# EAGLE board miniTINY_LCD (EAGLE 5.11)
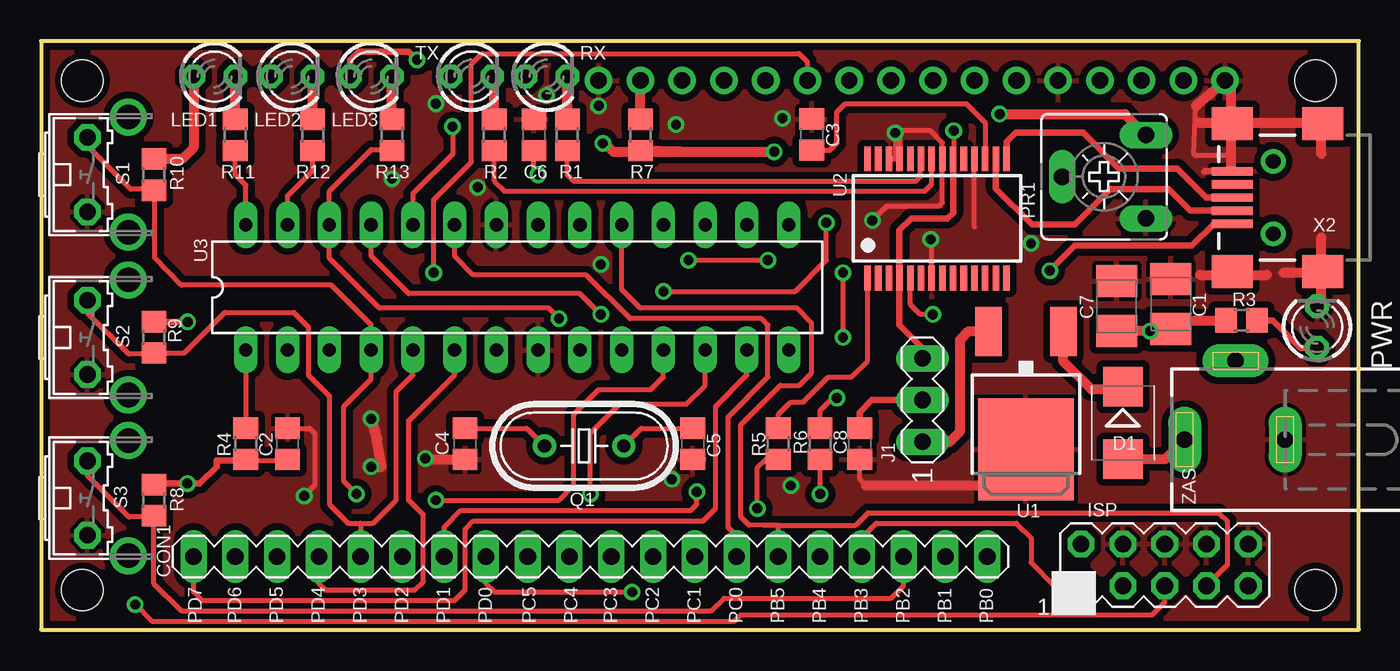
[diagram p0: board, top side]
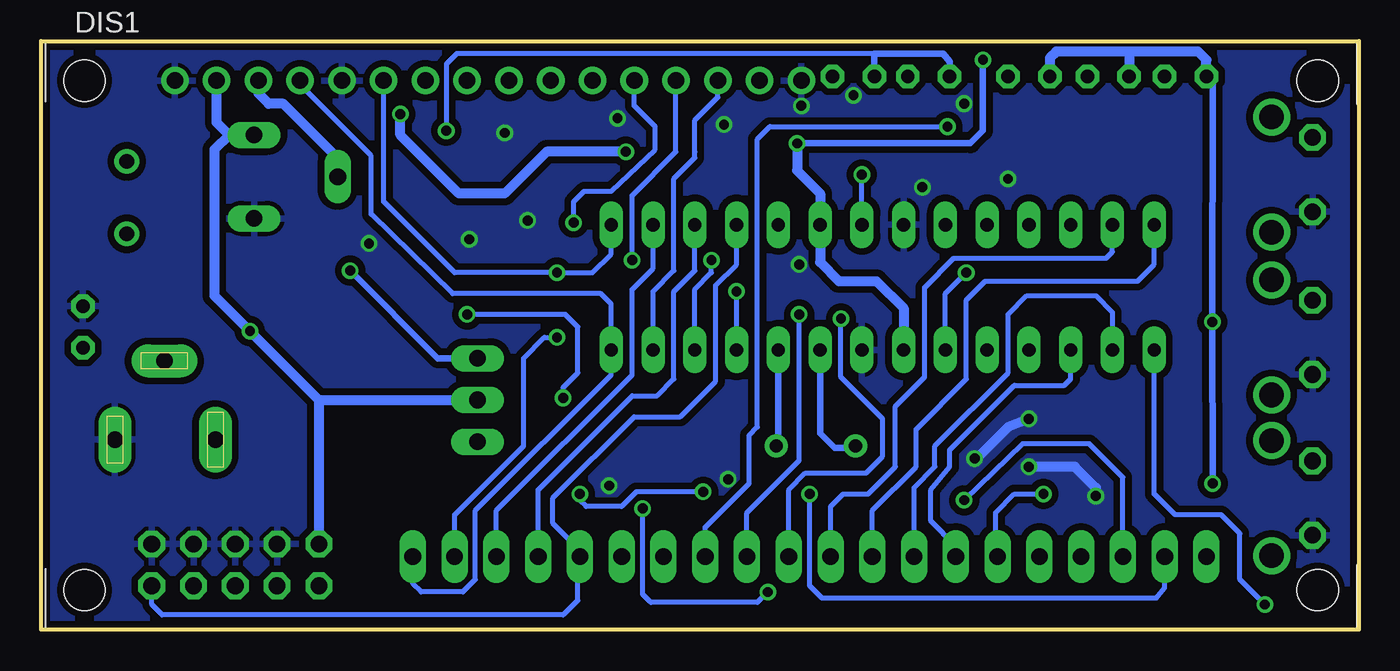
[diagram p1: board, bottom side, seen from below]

Size 80.14 x 35.81 mm. Coordinates in mm from the lower left corner, seen from the top.
Outline: 80.14,0 80.14,35.81 0,35.81 0,0 80.14,0
Copper layers (1*16): Top 0.035mm / dielectric 1.5mm / Bottom 0.035mm
Design rules "default *": minimum track width 8mil, minimum drill 16mil, track to track 8mil, track to pad 8mil, pad to pad 8mil, via to via 8mil, smd to smd 8mil, copper to edge 8mil, drill to drill 8mil, minimum pad ring 12mil, minimum via ring 8mil, stop-mask expansion 4mil, vias tented up to drill 18mil, thermal gap 10mil

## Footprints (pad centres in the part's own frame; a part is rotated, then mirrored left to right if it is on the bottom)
B/3528-21R = smd 1.95 x 2.5: + 1.525,0; - -1.525,0
C0805 = smd 1.3 x 1.5: 1 -0.95,0; 2 0.95,0
MA20-1 = drill 1.016 pad 1.473 long: 1 -24.13,0; 2 -21.59,0; 3 -19.05,0; 4 -16.51,0; 5 -13.97,0; 6 -11.43,0; 7 -8.89,0; 8 -6.35,0; 9 -3.81,0; 10 -1.27,0; 11 1.27,0; 12 3.81,0; 13 6.35,0; 14 8.89,0; 15 11.43,0; 16 13.97,0; 17 16.51,0; 18 19.05,0; 19 21.59,0; 20 24.13,0
SMB = smd 2.4 x 2.4: A 2.2,0; C -2.2,0
TUXGR_16X2_R2 = drill 1 pad 1.676 round: 1 -32,15.5; 2 -29.46,15.5; 3 -26.92,15.5; 4 -24.38,15.5; 5 -21.84,15.5; 6 -19.3,15.5; 7 -16.76,15.5; 8 -14.22,15.5; 9 -11.68,15.5; 10 -9.14,15.5; 11 -6.6,15.5; 12 -4.06,15.5; 13 -1.52,15.5; 14 1.02,15.5; 15 3.56,15.5; 16 6.1,15.5 | hole 2.5: -37.5,-15.5; 37.5,-15.5; -37.5,15.5; 37.5,15.5
MA05-2 = drill 1.016 octagon: 1 -5.08,-1.27; 2 -5.08,1.27; 3 -2.54,-1.27; 4 -2.54,1.27; 5 0,-1.27; 6 0,1.27; 7 2.54,-1.27; 8 2.54,1.27; 9 5.08,-1.27; 10 5.08,1.27
MA03-1 = drill 1.016 long: 1 -2.54,0; 2 0,0; 3 2.54,0
LED3MM = drill 0.813 octagon: A -1.27,0; K 1.27,0
CA6V = drill 1.016 long: A -2.54,-2.54; E 2.54,-2.54; S 0,2.54
HC49U70 = drill 0.813 round: 1 -2.413,0; 2 2.413,0
R0805 = smd 1.3 x 1.5: 1 -0.95,0; 2 0.95,0
B3F-31XX = drill 1.016 octagon: 1 -2.261,-1.245; 2 2.261,-1.245 | drill 1.499 pad 2.159 round: 3 -3.505,1.245; 4 3.505,1.245
DPACK = smd 1.6 x 3: 1 -2.28,-4.8; 3 2.28,-4.8 | smd 5.8 x 6.2: 4 0,2.38
SSOP28 = smd 0.4 x 1.5: 1 -4.225,-3.625; 2 -3.575,-3.625; 3 -2.925,-3.625; 4 -2.275,-3.625; 5 -1.625,-3.625; 6 -0.975,-3.625; 7 -0.325,-3.625; 8 0.325,-3.625; 9 0.975,-3.625; 10 1.625,-3.625; 11 2.275,-3.625; 12 2.925,-3.625; 13 3.575,-3.625; 14 4.225,-3.625; 15 4.225,3.625; 16 3.575,3.625; 17 2.925,3.625; 18 2.275,3.625; 19 1.625,3.625; 20 0.975,3.625; 21 0.325,3.625; 22 -0.325,3.625; 23 -0.975,3.625; 24 -1.625,3.625; 25 -2.275,3.625; 26 -2.925,3.625; 27 -3.575,3.625; 28 -4.225,3.625
DIL28-3 = drill 0.813 long: 1 -16.51,-3.81; 2 -13.97,-3.81; 3 -11.43,-3.81; 4 -8.89,-3.81; 5 -6.35,-3.81; 6 -3.81,-3.81; 7 -1.27,-3.81; 8 1.27,-3.81; 9 3.81,-3.81; 10 6.35,-3.81; 11 8.89,-3.81; 12 11.43,-3.81; 13 13.97,-3.81; 14 16.51,-3.81; 15 16.51,3.81; 16 13.97,3.81; 17 11.43,3.81; 18 8.89,3.81; 19 6.35,3.81; 20 3.81,3.81; 21 1.27,3.81; 22 -1.27,3.81; 23 -3.81,3.81; 24 -6.35,3.81; 25 -8.89,3.81; 26 -11.43,3.81; 27 -13.97,3.81; 28 -16.51,3.81
USB-MINIB-NOSTOP = smd 2.5 x 0.5: D+ 2.5,0; D- 2.5,0.8; GND 2.5,-1.6; ID 2.5,-0.8; VBUS 2.5,1.6 | smd 2.5 x 2: G1 -3,-4.5; G2 -3,4.5; G3 2.5,4.5; G4 2.5,-4.5 | drill 0.9 pad 0.8 round: H1 0,2.2 | drill 0.9 pad 0.787 round: H2 0,-2.2
DCJ0202 = drill 1 pad 2 long: 1 0,3.1; 2 4.8,0; 3 0,-3

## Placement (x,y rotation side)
C1  10uF  [B/3528-21R]  68.71,19.81 270 top
C2  100nF  [C0805]  14.99,11.3 90 top
C3  100nF  [C0805]  46.86,30.12 90 top
C4  22pF  [C0805]  25.78,11.3 270 top
C5  22pF  [C0805]  39.62,11.3 270 top
C6  100nF  [C0805]  29.97,30.1 90 top
C7  10uF  [B/3528-21R]  65.41,19.68 270 top
C8  100nF  [C0805]  49.78,11.3 270 top
CON1  [MA20-1]  33.4,4.45 0 top
D1  [SMB]  65.79,12.57 270 top
DIS1  [TUXGR_16X2_R2]  40.01,17.91 0 bottom
ISP  [MA05-2]  68.33,3.94 0 top
J1  [MA03-1]  53.59,13.97 90 top
LED1  [LED3MM]  10.54,33.66 0 top
LED2  [LED3MM]  15.24,33.66 0 top
LED3  [LED3MM]  20.07,33.66 0 top
PR1  10k  [CA6V]  64.64,27.56 90 top
PWR  [LED3MM]  77.6,18.41 90 top
Q1  [HC49U70]  33.02,11.18 0 top
R1  1k  [R0805]  32,30.1 270 top
R2  1k  [R0805]  27.56,30.1 270 top
R3  1k  [R0805]  73,18.82 180 top
R4  10k  [R0805]  12.45,11.3 90 top
R5  1k  [R0805]  44.83,11.3 90 top
R6  1k  [R0805]  47.37,11.3 90 top
R7  68  [R0805]  36.45,30.1 270 top
R8  10k  [R0805]  6.86,7.87 270 top
R9  10k  [R0805]  6.86,17.78 270 top
R10  10k  [R0805]  6.86,27.69 270 top
R11  1k  [R0805]  11.81,30.1 270 top
R12  1k  [R0805]  16.51,30.1 270 top
R13  1k  [R0805]  21.34,30.1 270 top
RX  [LED3MM]  30.73,33.66 0 top
S1  [B3F-31XX]  4.06,27.69 270 top
S2  [B3F-31XX]  4.06,17.78 270 top
S3  [B3F-31XX]  4.06,8 270 top
TX  [LED3MM]  26.16,33.66 0 top
U1  78M05  [DPACK]  59.89,13.34 180 top
U2  FT232RL  [SSOP28]  54.48,25.02 0 top
U3  MEGA8-P  [DIL28-3]  28.96,20.83 0 top
X2  USB-SMD-NS  [USB-MINIB-NOSTOP]  74.93,26.29 180 top
ZAS  [DCJ0202]  72.64,11.56 90 top

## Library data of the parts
C1-C8 R1-R13 = rcl
CON1 = con-lstb; OC_FARNELL: unknown; OC_NEWARK: unknown
D1 = diode
DIS1 = display-lcd; OC_FARNELL: unknown; OC_NEWARK: unknown
ISP = con-lstb
J1 = con-lstb_v2a; OC_FARNELL: unknown; OC_NEWARK: unknown
LED1-LED3 PWR RX TX = led
PR1 = pot
Q1 = crystal; OC_FARNELL: unknown; OC_NEWARK: unknown
S1-S3 = switch-omron; MPN: B3F-3100; OC_FARNELL: 959704; OC_NEWARK: 36M3582
U1 = v-reg
U2 = ftdichip; MPN: FT232RL; OC_FARNELL: 1146032; OC_NEWARK: 91K9918
U3 = atmel; OC_FARNELL: unknown; OC_NEWARK: unknown
X2 = SparkFun
ZAS = con-jack; OC_FARNELL: unknown; OC_NEWARK: unknown

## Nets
+5V: C1.+ C2.1 C7.+ C8.1 DIS1.2 ISP.2 J1.2 LED1.A LED2.A LED3.A PR1.E R3.2 R4.1 R7.2 R8.1 R9.1 R10.1 U3.7 U3.20
AREF: C6.1 U3.21
GND: C1.- C2.2 C3.2 C4.2 C5.2 C6.2 C7.- C8.2 DIS1.1 DIS1.5 DIS1.16 ISP.4 ISP.6 ISP.8 ISP.10 PR1.A PWR.K S1.2 S2.2 S3.2 U1.4 U2.7 U2.18 U2.21 U2.25 U2.26 U3.8 U3.22 X2.GND ZAS.3
N$1: C3.1 U2.17
N$2: D1.A ZAS.1
N$3: D1.C U1.1
N$4: R1.2 U2.23
N$5: PWR.A R3.1
N$6: R2.2 U2.22
N$7: J1.1 U1.3
N$8: R1.1 RX.K
N$9: R2.1 TX.K
N$10: LED1.K R11.1
N$11: LED2.K R12.1
N$12: DIS1.15 R7.1
N$13: LED3.K R13.1
N$14: DIS1.3 PR1.S
N$31: U2.15 X2.D+
N$32: U2.16 X2.D-
N$40: C5.1 Q1.2 U3.10
N$41: C4.1 Q1.1 U3.9
PB0: CON1.20 DIS1.4 U3.14
PB1: CON1.19 DIS1.6 U3.15
PB2: CON1.18 R8.2 S3.1 U3.16
PB3/MOSI: CON1.17 ISP.1 U3.17
PB4/MISO: CON1.16 ISP.9 U3.18
PB5/SCK: CON1.15 ISP.7 U3.19
PC0/A0: CON1.14 U3.23
PC1/A1: CON1.13 U3.24
PC2/A2: CON1.12 U3.25
PC3/A3: CON1.11 R13.2 U3.26
PC4/A4: CON1.10 R12.2 U3.27
PC5/A5: CON1.9 R11.2 U3.28
PD0/RX: CON1.8 R5.1 U3.2
PD1/TX: CON1.7 R6.1 U3.3
PD2: CON1.6 R10.2 S1.1 U3.4
PD3: CON1.5 R9.2 S2.1 U3.5
PD4: CON1.4 DIS1.11 U3.6
PD5: CON1.3 DIS1.12 U3.11
PD6: CON1.2 DIS1.13 U3.12
PD7: CON1.1 DIS1.14 U3.13
RESET: ISP.5 R4.2 U3.1
RX: R5.2 U2.1
TX: R6.2 U2.5
VUSB: J1.3 RX.A TX.A U2.4 U2.20 X2.VBUS

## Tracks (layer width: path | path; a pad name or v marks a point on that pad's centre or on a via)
+5V  (via drill 0.6)
  Top 0.305: 12.45,10.29 14.92,10.29 C2.1
  Top 0.406: C8.1 49.77,13.22 50.52,13.97 J1.2 | v22.86,34.67 22.35,35.18 19.3,35.18 18.8,34.67 LED3.A | R9.1 7.93,18.73 v8.91,18.72 | R4.1 12.45,10.29 10.67,10.29 10.67,9.91 9.65,8.89 v8.89,8.89 6.92,8.89 R8.1
  Top 0.61: C7.+ 68.58,18.16 C1.+ 69.24,18.82 | 69.24,18.82 R3.2 | 69.24,18.82 68.1,18.82 v67.44,18.16 | R10.1 8.57,28.64 9.27,29.34 LED1.A | v34.16,29.59 34.29,29.59 34.8,29.08 38.93,29.08 | 38.93,29.08 R7.2 | 38.93,29.08 v44.58,29.08 | v58.29,31.37 65.91,31.37 PR1.E
  Bottom 0.406: v22.86,34.67 22.86,30.35 23.62,29.59 v34.16,29.59 | LED1.A 8.89,33.27 v8.91,18.72 v8.89,8.89
  Bottom 0.61: LED1.A 9.27,34.67 9.78,35.18 14.1,35.18 | U3.7 27.69,19.56 29.34,21.21 31.62,21.21 32.77,22.35 U3.20 32.77,26.54 34.16,27.94 v34.16,29.59 | 14.1,35.18 18.41,35.18 18.8,34.8 LED3.A | LED2.A 13.97,35.05 14.1,35.18 | DIS1.2 69.47,30.86 68.71,30.1 | PR1.E 68.71,30.1 | 63.25,13.97 J1.2 | 68.71,30.1 69.6,29.21 69.6,20.32 v67.44,18.16 63.25,13.97 | 63.25,13.97 ISP.2 | v44.58,29.08 49.4,29.08 51.94,26.54 54.74,26.54 58.29,30.1 v58.29,31.37
AREF  (via drill 0.6)
  Top 0.305: v30.23,27.69 30.23,27.81 29.97,28.07 C6.1
  Bottom 0.305: U3.21 v30.23,27.69
GND  (via drill 0.6)
  Top 0.305: v51.94,30.23 51.94,28.65 U2.26 | C8.2 49.78,9.14 50.16,8.76 | 57.7,8.76 U1.4 | C2.2 16.32,12.25 16.64,11.94 16.64,8.76 v16,8.13 | U2.7 54.16,23.31 53.98,23.5 | v50.55,24.89 51.44,25.78 54.61,25.78 54.81,25.98 U2.21 54.81,29.65 54.1,30.35 52.07,30.35 v51.94,30.23 | 56.76,24.52 U2.18 | 72.02,33.41 DIS1.1 | 70.23,31.88 70.1,28.96 70.23,28.83 72.26,28.83 72.39,28.7 72.39,28.07 72.39,27.93 X2.GND | U2.25 52.21,29.96 v51.94,30.23
  Top 0.406: 71.35,27.89 70.76,27.89 70.74,27.86
  Top 0.61: 50.16,8.76 57.7,8.76 | v20.07,9.91 20.7,9.91 20.4,11.59 | 20.4,11.59 20.32,12.06 v20.07,12.83 20.45,11.63 20.4,11.59 | C4.2 23.43,10.35 v23.37,10.41 | 70.23,31.88 72.02,33.41 | 72.39,28.07 72.39,33.53 | 77.85,28.96 77.85,30.61 | 70.36,30.86 77.98,30.86 | 70.48,21.59 74.55,21.59 | 75.56,21.72 77.98,21.72 | 77.85,19.94 77.85,23.88
  Bottom 0.61: v16,8.13 16,8.64 17.27,9.91 v20.07,9.91 | v23.37,10.41 23.24,10.41 21.34,12.32 v20.07,12.83
  other vias: 26.54,26.92 38.35,9.14 33.91,31.88 34.04,22.23 21.34,27.43 24,32 38.61,30.73 30.73,32.51 45.09,31.11 60.2,23.5 54.1,23.75 45.59,8.76
  pour Bottom (isolate 0.406): -0.25,36.83 80.9,36.83 81.03,-0.51 -0.64,-0.51 -0.64,36.45
  pour Top (isolate 0.406): -1.02,36.58 80.9,36.2 81.28,-0.89 -0.76,-0.89
N$1
  Top 0.305: C3.1 47.97,29.17 48.39,29.59 48.39,31.5 48.9,32 56.26,32 57.4,30.86 U2.17
N$2
  Top 0.61: D1.A 68.36,10.37 ZAS.1
N$3
  Top 0.61: U1.1 62.17,16.31 63.88,14.61 65.62,14.61 D1.C
N$4
  Top 0.305: R1.2 32,27.69 32.38,27.3 53.21,27.3 53.47,27.56 53.47,28.6 U2.23 53.47,28.68
N$5
  Top 0.406: R3.1 74.91,18.82 76.58,17.14 PWR.A
N$6
  Top 0.305: U2.22 54.16,27.11 53.72,26.67 28.19,26.67 27.56,27.3 R2.2
N$7
  Top 0.61: J1.1 55.24,11.43 55.88,12.06 55.88,17.65 56.39,18.16 57.51,18.16 U1.3
N$8
  Top 0.61: R1.1 31.94,31.05 32,31.88 RX.K
N$9
  Top 0.61: TX.K 27.56,33.66 R2.1
N$10
  Top 0.61: R11.1 LED1.K
N$11
  Top 0.61: R12.1 LED2.K
N$12
  Top 0.61: DIS1.15 R7.1
N$13
  Top 0.61: R13.1 LED3.K
N$14
  Bottom 0.61: DIS1.3 66.92,32.63 66.29,32 65.41,32 62.1,28.7 PR1.S
N$31
  Top 0.406: X2.D+ 70.87,26.29 69.09,28.07 65.53,28.07 63.37,30.23 59.26,30.23 58.73,29.69 58.73,28.66 U2.15
N$32
  Top 0.406: X2.D- 69.89,25.49 68.58,26.8 65.02,26.8 62.87,24.64 60.27,24.64 58.06,26.85 U2.16
N$40
  Top 0.305: C5.1 36.51,12.25 Q1.2
  Bottom 0.406: U3.10 35.31,11.3 Q1.2
N$41
  Top 0.305: C4.1 29.53,12.25 Q1.1
  Bottom 0.406: U3.9 32.77,11.94 31.88,11.05 30.73,11.05 Q1.1
PB0
  Bottom 0.305: DIS1.4 64.39,33.27 64.39,33.15 60.07,28.83 60.07,25.27 55.12,20.45 46.1,20.45 45.47,19.81 U3.14 45.47,15.49 53.72,7.24 53.72,3.05 54.48,2.29 57.02,2.29 57.53,2.79 CON1.20
PB1  (via drill 0.6)
  Top 0.305: v48.77,17.78 v48.77,21.72
  Bottom 0.305: v48.77,17.78 49.53,17.78 50.8,16.51 50.8,11.18 54.99,6.99 CON1.19 | DIS1.6 59.31,26.04 54.99,21.72 v48.77,21.72 46.61,21.72 45.47,22.86 U3.15
PB2
  Top 0.305: S3.1 2.82,9.37 5.33,6.86 6.79,6.86 R8.2 6.86,2.79 8.51,1.14 40.77,1.14 41.53,1.91 51.69,1.91 52.45,2.67 CON1.18
  Bottom 0.305: U3.16 42.93,21.97 44.2,20.7 44.2,15.49 52.45,7.24 CON1.18
PB3/MOSI
  Top 0.305: ISP.1 61.59,2.67 60.2,4.06 60.2,5.59 59.31,6.48 50.8,6.48 49.91,5.59 CON1.17
  Bottom 0.305: U3.17 40.39,21.84 41.66,20.57 41.66,15.24 42.67,14.22 44.2,14.22 49.91,8.51 CON1.17
PB4/MISO
  Bottom 0.305: ISP.9 73.41,1.52 72.77,0.89 48.39,0.89 47.5,1.78 47.5,4.32 | CON1.16 47.37,4.83 49.02,6.48 49.02,8 44.07,12.95 41.27,12.95 39.12,15.11 39.12,20.95 37.85,22.23 U3.18
  Bottom 0.406: 47.5,4.32 CON1.16
PB5/SCK
  Top 0.305: U3.19 35.31,20.7 36.45,19.56 45.97,19.56 46.86,18.67 46.86,15.62 46.1,14.86 44.96,14.86 42.55,12.45 42.55,9.91 42.55,6.87 43.03,6.37 43.94,6.35 44.83,6.35 | ISP.7 72.14,3.94 72.14,6.6 71.63,7.11 50.29,7.11 49.53,6.35 44.83,6.35 | CON1.15 44.83,6.35
PC0/A0
  Top 0.305: CON1.14 42.29,5.71 41.78,6.22 41.78,12.95 44.2,15.37 44.2,18.54 43.81,18.92 35.81,18.92 33.15,21.59 26.29,21.59 25.15,22.73 U3.23
PC1/A1  (via drill 0.6)
  Top 0.305: v25.02,30.61 25.02,28.93 22.61,26.54 U3.24
  Bottom 0.305: CON1.13 39.75,6.22 37.08,8.89 37.08,11.81 36.58,12.32 36.58,29.84 35.81,30.61 v25.02,30.61
PC2/A2  (via drill 0.6)
  Top 0.305: v34.04,19.18 32.77,20.45 22.35,20.45 20.07,22.73 U3.25
  Bottom 0.305: CON1.12 37.21,7.11 34.04,10.29 v34.04,19.18
PC3/A3  (via drill 0.6)
  Top 0.305: v31.5,18.92 30.86,19.56 20.57,19.56 17.53,22.61 U3.26 17.53,26.67 20.07,29.21 21.27,29.21 R13.2
  Bottom 0.305: CON1.11 34.67,8.51 33.66,9.53 29.97,9.53 28.96,10.54 28.96,12.83 31.5,15.37 v31.5,18.92
PC4/A4
  Top 0.305: R12.2 16.51,27.94 14.99,26.42 U3.27
  Bottom 0.305: CON1.10 32.13,7.49 31.37,8.26 29.84,8.26 28.19,9.91 28.19,13.59 26.42,15.37 26.42,20.83 24.64,22.61 15.37,22.61 14.99,22.99 U3.27
PC5/A5
  Top 0.305: R11.2 11.81,27.69 12.45,27.05 U3.28
  Bottom 0.305: CON1.9 29.59,7.24 26.92,9.91 26.92,12.19 23.88,15.24 23.88,20.07 22.73,21.21 13.46,21.21 12.45,22.23 U3.28
PD0/RX  (via drill 0.6)
  Top 0.305: v43.56,7.37 43.56,9.86 44.07,10.36 R5.1 | v35.94,2.29 27.56,2.29 27.05,2.79 CON1.8
  Bottom 0.305: CON1.8 27.05,8.64 25.78,9.91 25.78,11.18 21.34,15.62 21.34,19.18 20.19,20.32 16,20.32 14.99,19.3 U3.2 | v43.56,7.37 43.56,2.16 43.05,1.65 36.58,1.65 v35.94,2.29
PD1/TX  (via drill 0.6)
  Top 0.305: CON1.7 24.51,6.22 25.53,7.24 39.5,7.24 39.88,7.62 v39.88,8.38 | v47.37,8.26 R6.1
  Bottom 0.305: CON1.7 24.51,5.08 26.04,6.6 26.04,8.51 24.89,9.91 24.89,10.92 20.95,14.86 17.91,14.86 17.53,15.24 U3.3 | v39.88,8.38 43.94,8.38 44.83,7.49 46.99,7.49 47.37,7.87 v47.37,8.26
PD2  (via drill 0.6)
  Top 0.305: v19.18,8.26 18.41,9.02 18.41,13.59 20.07,15.24 U3.4 20.07,18.54 17.65,20.95 8.53,20.95 6.91,22.63 6.92,26.8 R10.2 6.8,26.8 5.46,26.8 2.82,29.44 S1.1
  Bottom 0.305: v19.18,8.26 20.95,8.26 22.1,7.11 22.1,4.57 CON1.6
PD3
  Top 0.305: U3.5 22.61,15.49 21.59,14.48 21.59,7.87 20.19,6.48 19.43,6.48 | 19.43,6.48 CON1.5 | 19.43,6.48 18.67,6.48 17.53,7.62 17.53,14.22 16.26,15.49 16.26,18.41 15.37,19.3 11.18,19.3 8.7,16.83 R9.2 6.79,16.76 5.33,16.76 2.82,19.28 S2.1
PD4  (via drill 0.6)
  Top 0.305: U3.6 25.15,15.49 22.35,12.7 22.35,7.87 23.24,6.99 23.24,2.92 22.73,2.41 17.27,2.41 16.89,2.79 CON1.4 | DIS1.11 46.6,34.55 46.1,35.05 26.8,35.05 26.16,34.42 26.16,28.45 23.88,26.16 v23.88,21.72
  Bottom 0.305: v23.88,21.72 25.15,20.45 U3.6
PD5  (via drill 0.6)
  Top 0.305: v47.75,24.77 47.75,22.48 45.85,20.57 v37.85,20.57 | U3.11 37.85,15.37 37.08,14.61 33.91,14.61 32.38,13.08 32.38,8.76 31.5,7.87 v24,7.87
  Bottom 0.305: DIS1.12 44.07,31.88 42.8,30.61 42.8,29.21 45.47,26.67 47.12,26.67 47.75,26.04 47.75,25.53 v47.75,24.77 | U3.11 v37.85,20.57 | v24,7.87 20.45,11.3 16.38,11.3 14.35,9.27 CON1.3
PD6  (via drill 0.6)
  Top 0.305: v39.37,22.48 v44.2,22.48 | U3.12 40.39,14.86 39.24,13.72 35.18,13.72 33.4,11.94 v33.4,8.26
  Bottom 0.305: v44.2,22.48 44.2,26.42 41.53,29.08 DIS1.13 | v39.37,22.48 39.37,21.72 40.39,20.7 U3.12 | v33.4,8.26 33.4,2.67 32.64,1.91 12.32,1.91 11.81,2.54 CON1.2
PD7
  Top 0.305: CON1.1 9.27,2.29 9.78,1.78 25.15,1.78 25.78,2.41 25.78,6.1 26.29,6.6 40.26,6.6 41.02,7.37 41.02,13.59 42.93,15.49 U3.13
  Bottom 0.305: DIS1.14 38.98,32.39 40.39,30.99 40.39,29.08 40.38,28.71 41.66,27.43 41.66,21.84 42.93,20.57 U3.13
RESET  (via drill 0.6)
  Top 0.305: U3.1 R4.2 | ISP.5 68.33,1.65 67.56,0.89 42.55,0.89 42.16,0.51 6.73,0.51 v5.71,1.52
  Bottom 0.305: v5.71,1.52 7.24,3.05 7.24,5.84 8.38,6.99 11.18,6.99 12.45,8.26 U3.1
RX
  Top 0.305: U2.1 50.26,17.62 50.27,16.36 49.28,15.37 47.88,15.37 46.35,13.84 45.59,13.84 44.83,13.08 R5.2
TX  (via drill 0.6)
  Top 0.305: U2.5 52.86,19.84 52.86,19.79 53.47,19.18 v54.23,19.18 | v48.39,14.1 48.13,14.1 47.37,13.34 R6.2
  Bottom 0.305: v54.23,19.18 48.26,19.18 47.5,18.41 47.5,15.62 48.39,14.73 v48.39,14.1
VUSB  (via drill 0.6)
  Top 0.305: v55.5,30.35 55.5,28.68 U2.20
  Top 0.406: U2.20 55.46,25.36 55.12,25.02 52.91,25.02 52.2,24.31 52.2,21.41 | 52.2,21.41 U2.4 | X2.VBUS 71.3,24.69 69.98,23.37 62.87,23.37 v61.34,21.84 | 52.2,21.41 52.2,18.54 53.59,17.14 J1.3
  Bottom 0.305: 29.46,35.05 54.86,35.05 55.5,34.42 v55.5,30.35
  Bottom 0.406: v61.34,21.84 56.01,16.51 J1.3 | TX.A 24.89,34.54 25.27,35.05 29.46,35.05 RX.A

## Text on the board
tNames: 1 | PD7 | PD6 | PD5 | PD4 | PD3 | PD2 | PD1 | PD0 | PC5 | PC4 | PC3 | PC2 | PC1 | PC0 | PB5 | PB4 | PB3 | PB2 | PB1 | PB0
